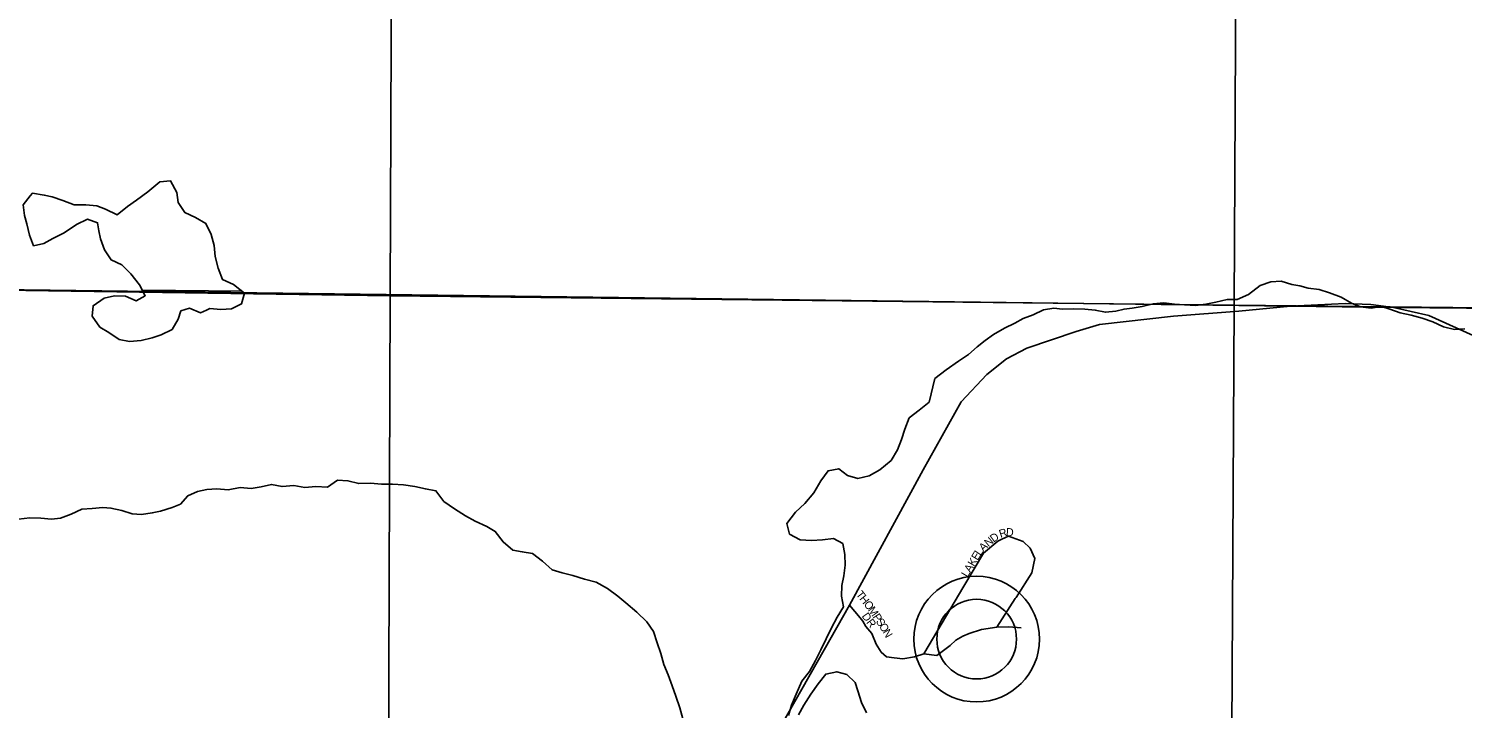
# Model space of a CAD drawing. Extents: x 2043100 to 2470832, y 443715 to 810583.
# Drawn here: x 2278495 to 2287455, y 688807 to 693056 of the extents above; entities that cross this region are included whole.
import ezdxf

# ---------------------------------------------------------------- set-up
doc = ezdxf.new("R2010")
doc.units = 0
for name, color, linetype in [('GM_X_Major_Lake', 7, 'Continuous'), ('GM_X_Section', 7, 'Continuous'), ('GM_X_State_Route', 7, 'Continuous'), ('GM_X_Township', 7, 'Continuous'), ('GM_X_Township_Subdivision', 7, 'Continuous'), ('GM_X_Township_Subdivision_Text', 7, 'Continuous'), ('GM_X_Unincorporated', 7, 'Continuous'), ('GM_X_Unincorporated_Location', 7, 'Continuous')]:
    doc.layers.add(name, color=color, linetype=linetype)

msp = doc.modelspace()

# ---------------------------------------------------------------- linework, layer by layer
at = {"layer": 'GM_X_Major_Lake'}
msp.add_line((2279827.9, 691414.5), (2279204.6, 691422.2), dxfattribs=at)
for points in [[(2278504.7, 692010.7), (2278518.6, 692026.8), (2278592.7, 692015.2), (2278642.7, 692005.5), (2278708.8, 691981.9), (2278779, 691954.2), (2278852.9, 691954.7), (2278921, 691949.1), (2278975.1, 691927.3), (2279049.2, 691891.7), (2279112.9, 691944.2), (2279168.7, 691984.5), (2279240.4, 692035), (2279314.1, 692097.5), (2279382, 692103.9), (2279420.4, 692032.1), (2279428.7, 691970), (2279471, 691906.2), (2279537.2, 691874.5), (2279603.4, 691838.9), (2279635.7, 691769), (2279654.1, 691701), (2279660.5, 691630.9), (2279678.9, 691558.9), (2279707.2, 691487), (2279775.4, 691457.4), (2279827.9, 691414.5)], [(2279606, 691296.5), (2279628.2, 691306.3), (2279696.2, 691300.7), (2279762.2, 691305.1), (2279826, 691335.5), (2279843.7, 691401.7), (2279775.4, 691457.4), (2279707.2, 691487), (2279678.9, 691558.9), (2279660.5, 691630.9), (2279654.1, 691701), (2279635.7, 691769), (2279603.4, 691838.9), (2279537.2, 691874.5), (2279471, 691906.2), (2279428.7, 691970), (2279420.4, 692032.1), (2279382, 692103.9), (2279314.1, 692097.5), (2279240.4, 692035), (2279168.7, 691984.5), (2279112.9, 691944.2), (2279049.2, 691891.7), (2278975.1, 691927.3), (2278921, 691949.1), (2278852.9, 691954.7), (2278779, 691954.2), (2278708.8, 691981.9), (2278642.7, 692005.5), (2278592.7, 692015.2), (2278518.6, 692026.8), (2278504.7, 692010.7)], [(2279204.6, 691422.2), (2279187.5, 691454), (2279133.2, 691523.8), (2279076.9, 691579.5), (2279010.7, 691611.2), (2278968.4, 691673), (2278944.1, 691742.9), (2278933.8, 691792.9), (2278925.5, 691843), (2278863.4, 691864.6), (2278793.6, 691832.2), (2278717.9, 691779.7), (2278646.1, 691743.2), (2278590.3, 691712.8), (2278526.4, 691698.5), (2278500.1, 691764.4), (2278483.7, 691836.4), (2278469.4, 691888.4), (2278461, 691954.4), (2278504.7, 692010.7)], [(2278504.7, 692010.7), (2278461, 691954.4)], [(2278483.7, 691836.4), (2278500.1, 691764.4), (2278526.4, 691698.5), (2278590.3, 691712.8), (2278646.1, 691743.2), (2278717.9, 691779.7), (2278793.6, 691832.2), (2278863.4, 691864.6), (2278925.5, 691843), (2278933.8, 691792.9), (2278944.1, 691742.9), (2278968.4, 691673), (2279010.7, 691611.2), (2279076.9, 691579.5), (2279133.2, 691523.8), (2279187.5, 691454), (2279223.9, 691386.1), (2279166.1, 691353.7), (2279099.9, 691383.4), (2279032, 691385), (2278968, 691370.6), (2278898.3, 691324.1), (2278892.7, 691258), (2278941, 691190.2), (2278995.2, 691156.5), (2279061.4, 691112.8), (2279125.5, 691101.2), (2279197.4, 691105.6), (2279267.3, 691124), (2279323.2, 691142.4), (2279391, 691174.8), (2279428.6, 691239.1), (2279446.4, 691291.3), (2279500.2, 691309.6), (2279568.4, 691279.9), (2279606, 691296.5)], [(2279204.6, 691422.2), (2279223.9, 691386.1), (2279166.1, 691353.7), (2279099.9, 691383.4), (2279032, 691385), (2278968, 691370.6), (2278898.3, 691324.1), (2278892.7, 691258), (2278941, 691190.2), (2278995.2, 691156.5), (2279061.4, 691112.8), (2279125.5, 691101.2), (2279197.4, 691105.6), (2279267.3, 691124), (2279323.2, 691142.4), (2279391, 691174.8), (2279428.6, 691239.1), (2279446.4, 691291.3), (2279500.2, 691309.6), (2279568.4, 691279.9), (2279606, 691296.5)], [(2279606, 691296.5), (2279628.2, 691306.3), (2279696.2, 691300.7), (2279762.2, 691305.1), (2279826, 691335.5), (2279843.7, 691401.7), (2279827.9, 691414.5)], [(2284157.4, 690868.8), (2284229.4, 690923), (2284305.5, 690977.2), (2284367.6, 691019.4), (2284423.6, 691067.5), (2284473.6, 691105.7), (2284525.7, 691143.8), (2284593.7, 691184), (2284657.8, 691214.2), (2284709.8, 691244.3), (2284771.9, 691266.5), (2284838, 691298.6), (2284902.1, 691308.7), (2284956.1, 691302.8), (2285024.2, 691304.9), (2285096.3, 691303), (2285160.4, 691297.1), (2285224.5, 691283.2), (2285288.5, 691289.3), (2285340.6, 691303.4), (2285390.7, 691309.5), (2285454.7, 691319.6), (2285522.8, 691335.7), (2285588.9, 691341.8), (2285657, 691333.9), (2285719.1, 691330), (2285787.1, 691326.1), (2285851.2, 691334.2), (2285915.3, 691346.3), (2285985.4, 691362.5), (2286047.5, 691362.6), (2286117.5, 691394.7), (2286191.6, 691451), (2286257.6, 691473.1), (2286321.7, 691477.2), (2286389.8, 691457.3), (2286439.9, 691447.3), (2286492, 691433.4), (2286560, 691425.5), (2286624.1, 691405.5), (2286698.3, 691377.6), (2286762.3, 691339.6), (2286818.4, 691317.7), (2286884.5, 691309.7), (2286950.6, 691319.9), (2287000.7, 691301.9), (2287066.8, 691279.9), (2287134.9, 691264), (2287202.9, 691246.1), (2287271, 691224.2), (2287337.1, 691192.2), (2287405.2, 691176.3), (2287471.3, 691180.4)], [(2283244.7, 688763.5), (2283262.3, 688827.7), (2283291.9, 688895.9), (2283327.4, 688978.3), (2283375, 689038.7), (2283412.5, 689107), (2283446.1, 689173.3), (2283513.3, 689309.9), (2283548.9, 689378.2), (2283588.4, 689442.5), (2283574.1, 689508.5), (2283577.7, 689574.6), (2283589.3, 689634.8), (2283596.9, 689702.9), (2283596.5, 689769), (2283584.1, 689837), (2283524, 689868.7), (2283456.1, 689860.2), (2283388.2, 689855.8), (2283316.2, 689861.3), (2283250.1, 689896.9), (2283233.7, 689962.9), (2283287.2, 690033.4), (2283344.9, 690087.8), (2283402.4, 690154.2), (2283446, 690228.6), (2283491.6, 690293), (2283557.4, 690305.4), (2283611.6, 690263.7), (2283677.7, 690244.1), (2283747.5, 690260.6), (2283815.3, 690299.1), (2283884.9, 690357.6), (2283924.5, 690423.9), (2283950.1, 690488.2), (2283971.7, 690552.4), (2283997.2, 690622.6), (2284060.9, 690671.1), (2284122.6, 690721.5), (2284157.4, 690868.8)], [(2279444, 690083), (2279489.6, 690135.4), (2279549.4, 690161.8), (2279609.3, 690176.2), (2279671.2, 690178.6), (2279741.2, 690173), (2279817.1, 690187.5), (2279885.1, 690181.9), (2279948.9, 690192.4), (2280012.8, 690206.8), (2280078.8, 690193.2), (2280152.7, 690199.7), (2280220.8, 690188.1), (2280290.7, 690194.5), (2280362.6, 690189), (2280424.3, 690233.4), (2280490.3, 690229.8), (2280558.3, 690212.3), (2280632.3, 690214.7), (2280700.3, 690209.2), (2280768.2, 690207.6), (2280838.2, 690204), (2280908.2, 690194.4), (2280974.2, 690178.8), (2281040.2, 690167.3), (2281090.6, 690099.5), (2281156.8, 690053.9), (2281225, 690010.2), (2281285.2, 689976.6), (2281359.3, 689945), (2281411.4, 689913.3), (2281459.8, 689847.5), (2281520, 689795.8), (2281580, 689786.2), (2281644, 689774.6), (2281706.3, 689726.9), (2281766.5, 689673.2), (2281828.6, 689653.6), (2281896.6, 689638), (2281968.7, 689614.4), (2282040.8, 689596.9), (2282112.9, 689557.3), (2282177.2, 689509.6), (2282227.4, 689467.9), (2282295.7, 689408.3), (2282358, 689348.6), (2282400.3, 689286.8), (2282422.7, 689216.8), (2282445.1, 689150.9), (2282465.4, 689080.9), (2282491.8, 689017), (2282516.2, 688947.1), (2282538.6, 688883.1), (2282564.9, 688811.2), (2282583.3, 688741.2)], [(2278431.6, 689989.7), (2278501.5, 689998.1), (2278571.5, 689996.5), (2278637.5, 689990.9), (2278693.5, 689995.2), (2278761.4, 690021.7), (2278827.2, 690052.1), (2278891.1, 690056.5), (2278959.1, 690062.9), (2279009.1, 690059.2), (2279077.2, 690043.5), (2279141.2, 690023.9), (2279201.3, 690018.2), (2279267.2, 690028.6), (2279319.1, 690038.9), (2279391, 690063.4), (2279444, 690083)], [(2283732.2, 688778.6), (2283699.8, 688844.5), (2283677.5, 688916.4), (2283661.2, 688968.4), (2283608.9, 689018.1), (2283544.9, 689035.7), (2283477, 689021.3), (2283429.4, 688960.9), (2283383.8, 688896.5), (2283340.2, 688828.2), (2283306.6, 688765.9)]]:
    msp.add_lwpolyline(points, dxfattribs=at)
at = {"layer": 'GM_X_Section'}
for points in [[(2280774.6, 696731.3), (2280753.4, 691386.7), (2275486.2, 691462.8), (2275505.4, 696803.3)], [(2280774.6, 696731.3), (2286056.9, 696655.8), (2286029, 691327), (2280753.4, 691386.7)], [(2286056.9, 696655.8), (2291354, 696607.4), (2291332.5, 693981.9), (2291298.1, 691272.2), (2286029, 691327)], [(2275486.2, 691462.8), (2280753.4, 691386.7), (2280735.8, 686074.1), (2275452.6, 686156)], [(2280753.4, 691386.7), (2286029, 691327), (2285999.1, 685990.1), (2280735.8, 686074.1)], [(2286029, 691327), (2291298.1, 691272.2), (2291263.2, 688598.5), (2291224.3, 685932.8), (2285999.1, 685990.1)]]:
    msp.add_lwpolyline(points, close=True, dxfattribs=at)
at = {"layer": 'GM_X_State_Route'}
msp.add_lwpolyline([(2281833.1, 686400.8), (2281833.9, 686402), (2282149, 686849), (2283465.6, 689172.1), (2283624.2, 689451.9), (2284085.8, 690297.9), (2284322.1, 690722.8), (2284482.2, 690893.7), (2284605.3, 690991.9), (2284732.9, 691058), (2285040.6, 691163), (2285186.6, 691206.3), (2285649.1, 691258.9), (2286058.9, 691289), (2286380.6, 691321.2), (2286722.5, 691337.9), (2286882.3, 691332.3), (2287025.2, 691312.9), (2287245.2, 691262.7), (2287587.4, 691108.5)], dxfattribs=at)
at = {"layer": 'GM_X_Township'}
for points in [[(2293731.2, 693440.2), (2293647.8, 685708.5), (2293607.5, 683205.3), (2291154.9, 683245.7), (2291293, 689692.2), (2291309.7, 691274.3), (2290302.8, 691283.4), (2290214.7, 691284.2), (2287025.2, 691312.9), (2286380.6, 691321.2), (2276849.9, 691444)], [(2258742.3, 671669), (2258825.8, 676651), (2258961.3, 683177.1), (2259026, 687904.9), (2259058.8, 688587.4), (2259077.8, 691690.4), (2260528, 691671), (2264160.5, 691637.7), (2264208.8, 691639.2), (2264826.1, 691636.2), (2265625, 691610.1), (2266028.8, 691606.1), (2272742.6, 691497), (2274137.9, 691479), (2276849.9, 691444), (2286380.6, 691321.2), (2287025.2, 691312.9), (2290214.7, 691284.2), (2290302.8, 691283.4), (2291309.7, 691274.3), (2291293, 689692.2), (2291154.9, 683245.7), (2291206.9, 678354.6), (2291162.8, 672835.5)]]:
    msp.add_lwpolyline(points, dxfattribs=at)
at = {"layer": 'GM_X_Township_Subdivision'}
for points in [[(2284661.2, 689493.8), (2284665.8, 689501), (2284765.1, 689653.9), (2284782.5, 689744.1), (2284754, 689808), (2284709.7, 689849.8), (2284619.5, 689883.2), (2284600.2, 689874.5)], [(2284600.2, 689874.5), (2284572.5, 689862.1), (2284551.7, 689852.7), (2284462.2, 689777.9), (2284339.7, 689570.6), (2284088.6, 689147.6)], [(2284697.6, 689310.8), (2284621.5, 689316.2), (2284545.5, 689315.7), (2284449.6, 689301), (2284371.8, 689274.3), (2284333.9, 689258), (2284290.1, 689233.7), (2284254.4, 689199.4), (2284170.8, 689136.7), (2284088.6, 689147.6), (2284030.9, 689130.3), (2283958.8, 689117.3), (2283904, 689123.1), (2283856.4, 689130.3), (2283823.2, 689159.2), (2283791.5, 689208.2), (2283764.1, 689274.5), (2283726.5, 689319.7), (2283708.5, 689351.7), (2283692.4, 689373.7), (2283624.2, 689451.9)], [(2284545.5, 689315.7), (2284661.2, 689493.8)]]:
    msp.add_lwpolyline(points, dxfattribs=at)
at = {"layer": 'GM_X_Unincorporated'}
for radius in [392.8, 249]:
    msp.add_circle((2284419.6, 689240.1), radius, dxfattribs=at)
at = {"layer": 'GM_X_Unincorporated_Location'}
msp.add_line((2284419.6, 689240.1), (2284419.6, 689240.1), dxfattribs=at)

# ---------------------------------------------------------------- texts
at = {"layer": 'GM_X_Township_Subdivision_Text'}
for s, rotation, p in [('D', 36.51584, (2284525.9, 689842)), ('R', 18.43495, (2284569.2, 689872.4)), ('D', 358.77601, (2284602.3, 689884.3)), ('L', 55.92347, (2284443.4, 689757.8)), ('A', 42.97499, (2284461.1, 689784.7)), ('N', 40.03227, (2284492.8, 689814.2)), ('K', 58.99838, (2284403, 689690.5)), ('E', 59.00813, (2284425.6, 689728.2)), ('L', 59.00813, (2284362.1, 689622.6)), ('A', 58.98377, (2284380.3, 689652.7)), ('T', 308.16491, (2283662.3, 689518.8)), ('H', 308.17857, (2283684.1, 689491.2)), ('O', 308.17857, (2283711.2, 689456.6)), ('M', 304.53386, (2283737.9, 689422.6)), ('DR', 306.24942, (2283699, 689383.3)), ('P', 303.94011, (2283767.8, 689379.3)), ('S', 303.91744, (2283787.4, 689350.1)), ('O', 302.61704, (2283806.9, 689321.1)), ('N', 299.75302, (2283830.3, 689284.6))]:
    msp.add_text(s, height=50, rotation=rotation, dxfattribs=at).set_placement(p)

doc.saveas('drawing.dxf')
